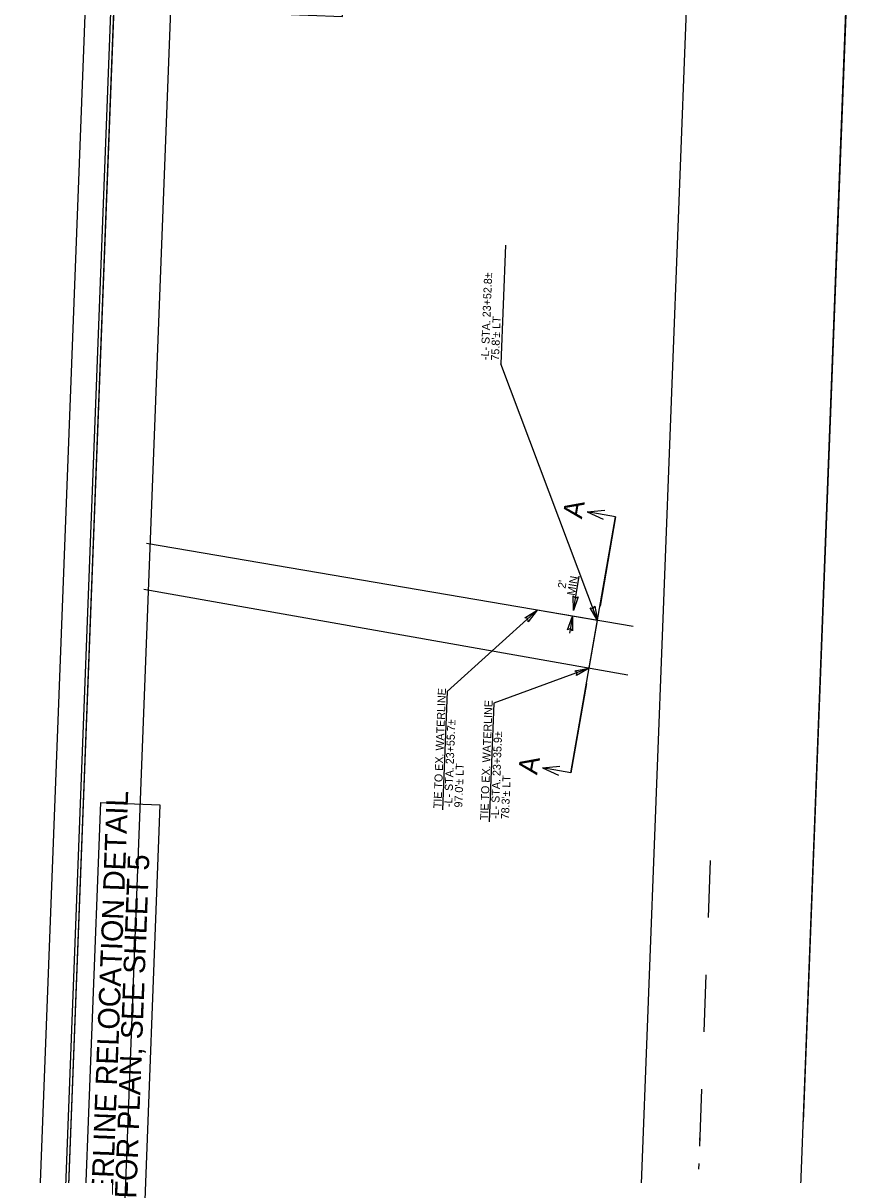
# Model space of a CAD drawing. Extents: x 2097431 to 2097897, y 685861 to 686794.
# Drawn here: x 2097431.2 to 2097727, y 686180.1 to 686582.8 of the extents above; entities that cross this region are included whole.
import ezdxf

# ---------------------------------------------------------------- set-up
doc = ezdxf.new("R2010")
doc.units = 0
for name, color, linetype in [('Old_Level_10', 7, 'Continuous'), ('Prop Dimension', 7, 'Continuous'), ('Prop Terminator CELL', 7, 'Continuous'), ('Scratch_Level_3', 7, 'Continuous'), ('Scratch_Level_4', 7, 'Continuous'), ('Scratch_Level_5', 7, 'Continuous'), ('Sheet Layout Plan Border', 7, 'Continuous'), ('Sheet Plan And Profile CELL', 7, 'Continuous'), ('Sheet Plot Border Inside CELL', 7, 'Continuous'), ('Sheet Plot Border Outside CELL', 7, 'Continuous'), ('Sheet Profile CELL', 7, 'Continuous'), ('Sheet Profile Grid Middle CELL', 7, 'Continuous'), ('Sheet Profile Grid Minor CELL', 7, 'Continuous')]:
    doc.layers.add(name, color=color, linetype=linetype)

msp = doc.modelspace()

# ---------------------------------------------------------------- linework, layer by layer
at = {"layer": 'Old_Level_10'}
for p, q in [((2097628.47, 686411.95), (2097634.6, 686412.51)), ((2097628.47, 686411.95), (2097634.05, 686409.34)), ((2097638.4, 686410.21), (2097628.47, 686411.95)), ((2097638.4, 686410.21), (2097632.95, 686379.01)), ((2097632.07, 686373.98), (2097611.02, 686377.56)), ((2097629.14, 686357.25), (2097632.07, 686373.98)), ((2097628.21, 686351.93), (2097622.75, 686320.73)), ((2097612.82, 686322.46), (2097618.95, 686323.02)), ((2097622.75, 686320.73), (2097612.82, 686322.46)), ((2097612.82, 686322.46), (2097618.4, 686319.86))]:
    msp.add_line(p, q, dxfattribs=at)
at = {"layer": 'Prop Dimension'}
for p, q in [((2097599.85, 686505.13), (2097598.26, 686463.72)), ((2097632.07, 686373.98), (2097598.26, 686463.72)), ((2097623.65, 686377.44), (2097625.7, 686389.48)), ((2097611.02, 686377.56), (2097579.45, 686349.13)), ((2097623.32, 686375.47), (2097622.31, 686369.55)), ((2097629.15, 686357.24), (2097595.77, 686344.99)), ((2097579.45, 686349.13), (2097577.86, 686307.72)), ((2097595.77, 686344.99), (2097594.18, 686303.58))]:
    msp.add_line(p, q, dxfattribs=at)
at = {"layer": 'Prop Terminator CELL'}
for points in [[(2097625.35, 686382.23), (2097623.65, 686377.43), (2097623.62, 686382.56), (2097624.39, 686381.78)], [(2097631.11, 686378.97), (2097632.07, 686373.97), (2097629.46, 686378.38), (2097630.52, 686378.09)], [(2097606.72, 686374.85), (2097611.03, 686377.57), (2097607.88, 686373.53), (2097607.76, 686374.62)], [(2097621.62, 686370.67), (2097623.32, 686375.48), (2097623.35, 686370.35), (2097622.58, 686371.13)], [(2097624.15, 686356.33), (2097629.16, 686357.25), (2097624.73, 686354.67), (2097625.02, 686355.73)]]:
    msp.add_lwpolyline(points, close=True, dxfattribs=at)
at = {"layer": 'Scratch_Level_3'}
msp.add_line((2097622.75, 686320.73), (2097638.4, 686410.21), dxfattribs=at)
at = {"layer": 'Scratch_Level_4'}
msp.add_lwpolyline([(2097452.11, 686147.63), (2097458.35, 686310.29), (2097479.08, 686309.5), (2097472.84, 686146.83)], close=True, dxfattribs=at)
at = {"layer": 'Scratch_Level_5'}
for p, q in [((2097644.59, 686371.85), (2097474.36, 686400.81)), ((2097642.67, 686354.86), (2097473.46, 686384.79))]:
    msp.add_line(p, q, dxfattribs=at)
msp.add_lwpolyline([(2097443.76, 686088.61), (2097699.44, 686078.8), (2097722.44, 686678.36), (2097503.65, 686686.75), (2097500.59, 686606.79), (2097463.68, 686608.21)], close=True, dxfattribs=at)
at = {"layer": 'Sheet Layout Plan Border'}
msp.add_lwpolyline([(2097644.38, 686100.93), (2097464.51, 686107.83), (2097482.9, 686587.46), (2097542.88, 686585.16), (2097545.95, 686665.12), (2097665.84, 686660.52)], close=True, dxfattribs=at)
at = {"layer": 'Sheet Plan And Profile CELL'}
msp.add_lwpolyline([(2097466.75, 686688.17), (2097443.76, 686088.61), (2097863.45, 686072.51), (2097886.44, 686672.07)], close=True, dxfattribs=at)
at = {"layer": 'Sheet Plot Border Inside CELL'}
msp.add_lwpolyline([(2097862.11, 686010.92), (2097887.65, 686677.03), (2097465.92, 686693.2), (2097440.38, 686027.09)], close=True, dxfattribs=at)
at = {"layer": 'Sheet Plot Border Outside CELL'}
msp.add_lwpolyline([(2097870.88, 686005.38), (2097896.7, 686678.48), (2097457.02, 686695.35), (2097431.2, 686022.24)], close=True, dxfattribs=at)
at = {"layer": 'Sheet Profile CELL'}
msp.add_line((2097722.44, 686678.36), (2097704.04, 686198.72), dxfattribs=at)
msp.add_lwpolyline([(2097466.75, 686688.17), (2097443.76, 686088.61), (2097863.45, 686072.51), (2097886.44, 686672.07)], close=True, dxfattribs=at)
at = {"layer": 'Sheet Profile Grid Middle CELL'}
for p, q in [((2097670.88, 686270.04), (2097671.64, 686290.02)), ((2097669.34, 686230.07), (2097670.11, 686250.05)), ((2097667.81, 686190.1), (2097668.58, 686210.08))]:
    msp.add_line(p, q, dxfattribs=at)
at = {"layer": 'Sheet Profile Grid Minor CELL'}
for p, q in [((2097667.89, 686192.1), (2097667.96, 686194.09)), ((2097667.5, 686182.1), (2097667.58, 686184.1))]:
    msp.add_line(p, q, dxfattribs=at)

# ---------------------------------------------------------------- texts
at = {"layer": 'Old_Level_10'}
for s, height, rotation, p in [('-L- STA. 23+52.8%%P', 2.7985, 87.8037, (2097594.08, 686464.97)), ("75.8'%%P LT", 2.7985, 87.8037, (2097597.62, 686464.79)), ('A', 6.88, 80.0777, (2097626.6, 686409.27)), ("2'", 2.798, 80.4954, (2097620.87, 686385)), ('MIN', 2.798, 80.4954, (2097624.14, 686382.51)), ('TIE TO EX. WATERLINE', 2.7985, 87.8037, (2097577.49, 686308.25)), ('TIE TO EX. WATERLINE', 2.7985, 87.8037, (2097593.81, 686304.1)), ('-L- STA. 23+55.7%%P', 2.7985, 87.8037, (2097581.24, 686308.68)), ('-L- STA. 23+35.9%%P', 2.7985, 87.8037, (2097597.56, 686304.54)), ('A', 6.88, 80.0777, (2097610.94, 686319.79)), ("97.0'%%P LT", 2.7985, 87.8037, (2097584.78, 686308.51)), ("78.3'%%P LT", 2.7985, 87.8037, (2097601.1, 686304.37))]:
    msp.add_text(s, height=height, rotation=rotation, dxfattribs=at).set_placement(p)
at = {"layer": 'Prop Dimension'}
for s, p in [('WATERLINE RELOCATION DETAIL', (2097461.7, 686150.03)), ('FOR PLAN, SEE SHEET 5', (2097470.78, 686171.72))]:
    msp.add_text(s, height=7.5, rotation=87.8037, dxfattribs=at).set_placement(p)

doc.saveas('drawing.dxf')
